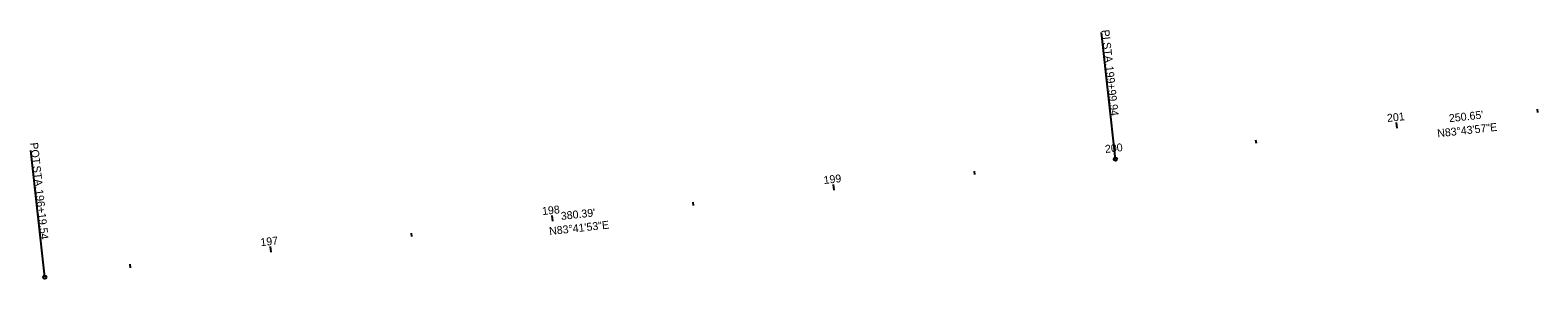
# Model space of a CAD drawing. Extents: x 1600023 to 1602131, y 285824 to 287284.
# Drawn here: x 1600023 to 1600555, y 286534 to 286622 of the extents above; entities that cross this region are included whole.
import ezdxf

# ---------------------------------------------------------------- set-up
doc = ezdxf.new("R2010")
doc.units = 0
for name, color, linetype in [('PM_P_CL_Double_Solid', 7, 'Continuous'), ('PM_P_Dotted_Line', 7, 'Continuous'), ('PM_P_Edge_Line', 7, 'Continuous'), ('PM_P_Transverse_Line', 7, 'Continuous')]:
    doc.layers.add(name, color=color, linetype=linetype)

msp = doc.modelspace()

# ---------------------------------------------------------------- linework, layer by layer
at = {"layer": 'PM_P_CL_Double_Solid'}
for p, q in [((1600406.13, 286576.06), (1600401.22, 286620.8)), ((1600028.03, 286534.31), (1600023.1, 286579.04))]:
    msp.add_line(p, q, dxfattribs=at)
for centre in [(1600406.13, 286576.06), (1600028.03, 286534.31)]:
    msp.add_circle(centre, 0.6, dxfattribs=at)
at = {"layer": 'PM_P_Transverse_Line'}
for p, q in [((1600555.3, 286592.45), (1600555.17, 286593.64)), ((1600505.59, 286586.99), (1600505.38, 286588.98)), ((1600455.89, 286581.53), (1600455.76, 286582.72)), ((1600406.19, 286576.07), (1600405.97, 286578.06)), ((1600306.8, 286565.1), (1600306.58, 286567.08)), ((1600356.49, 286570.58), (1600356.36, 286571.78)), ((1600207.4, 286554.12), (1600207.18, 286556.11)), ((1600257.1, 286559.61), (1600256.97, 286560.8)), ((1600157.7, 286548.63), (1600157.57, 286549.82)), ((1600108.01, 286543.14), (1600107.79, 286545.13)), ((1600058.31, 286537.65), (1600058.18, 286538.85))]:
    msp.add_line(p, q, dxfattribs=at)

# ---------------------------------------------------------------- texts
at = {"layer": 'PM_P_CL_Double_Solid'}
for s, rotation, p in [('PI', 276.2675, (1600401.17, 286621.61)), (' STA. ', 276.2675, (1600401.54, 286618.24)), ('199+99.94', 276.2675, (1600402.57, 286608.85)), ('POT', 276.3018, (1600022.84, 286581.75)), (' STA. ', 276.3018, (1600023.63, 286574.59)), ('196+19.54', 276.3018, (1600024.67, 286565.2))]:
    msp.add_text(s, height=2.8, rotation=rotation, dxfattribs=at).set_placement(p)
at = {"layer": 'PM_P_Dotted_Line'}
for s, rotation, p in [("250.65'", 6.2675, (1600524.06, 286589.06)), ("380.39'", 6.3018, (1600210.44, 286554.5))]:
    msp.add_text(s, height=2.8, rotation=rotation, dxfattribs=at).set_placement(p)
at = {"layer": 'PM_P_Edge_Line'}
for s, rotation, p in [('N83°43\'57"E', 6.2675, (1600519.93, 286583.73)), ('N83°41\'53"E', 6.3018, (1600206.31, 286549.17))]:
    msp.add_text(s, height=2.8, rotation=rotation, dxfattribs=at).set_placement(p)
at = {"layer": 'PM_P_Transverse_Line'}
for s, rotation, p in [('201', 6.2675, (1600502.19, 286589.13)), ('200', 6.2675, (1600402.59, 286578.19)), ('199', 6.3018, (1600303.22, 286567.22)), ('198', 6.3018, (1600203.81, 286556.24)), ('197', 6.3018, (1600104.34, 286545.25))]:
    msp.add_text(s, height=2.8, rotation=rotation, dxfattribs=at).set_placement(p)

doc.saveas('drawing.dxf')
